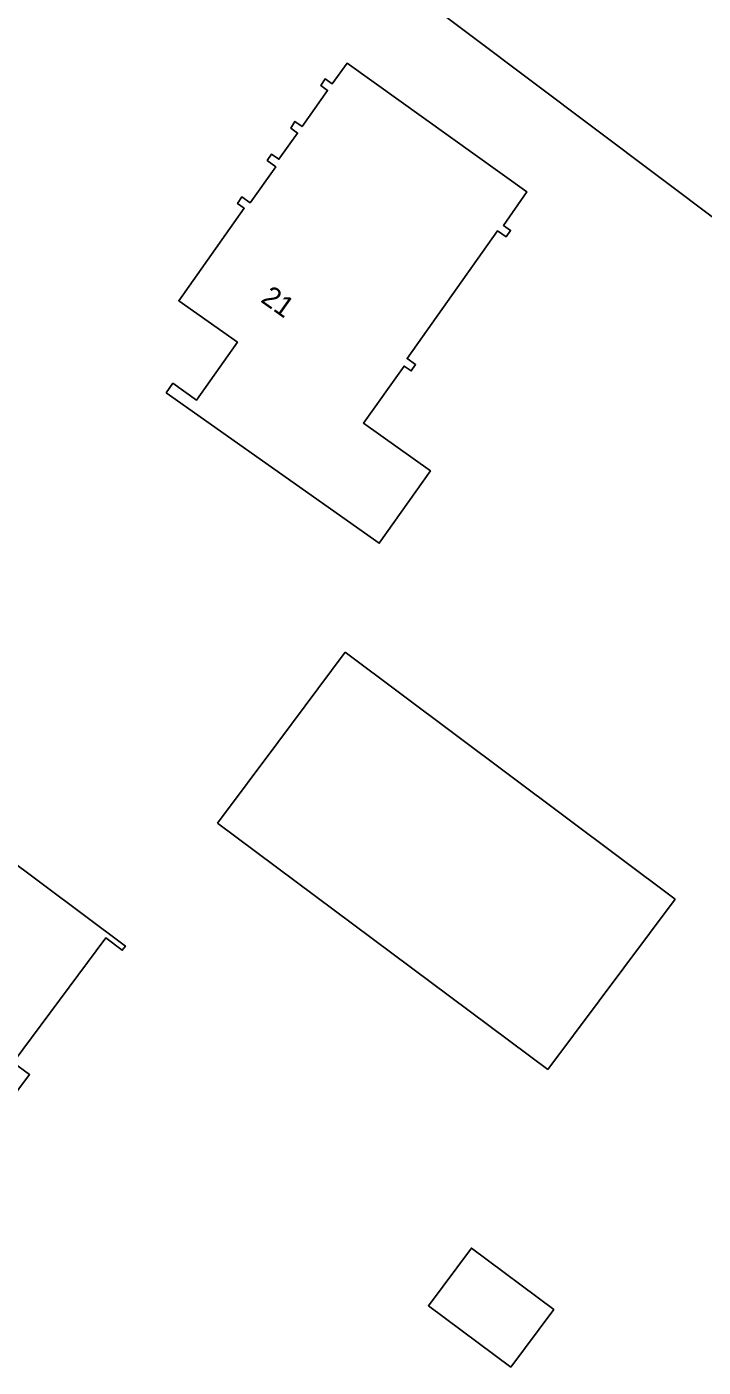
# Model space of a CAD drawing. Extents: x 136000 to 141000, y 400494 to 402006.
# Drawn here: x 137180.1 to 137213, y 400744.6 to 400809.8 of the extents above; entities that cross this region are included whole.
import ezdxf

# ---------------------------------------------------------------- set-up
doc = ezdxf.new("R2010")
doc.units = 0
for name, color, linetype in [('gg-anno-huisnummerreeks BGT', 7, 'Continuous'), ('gg-bbg-gedigitaliseerde bijgebouw', 7, 'Continuous'), ('gg-bbg-hoofdgebouw', 7, 'Continuous'), ('gg-knt-bronhoudergrens', 7, 'Continuous')]:
    doc.layers.add(name, color=color, linetype=linetype)

msp = doc.modelspace()

# ---------------------------------------------------------------- linework, layer by layer
at = {"layer": 'gg-bbg-gedigitaliseerde bijgebouw'}
for p, q in [((137192.334, 400774.993), (137195.608, 400779.388)), ((137195.608, 400779.388), (137211.678, 400767.36)), ((137189.403, 400771.058), (137192.334, 400774.993)), ((137205.484, 400759.079), (137189.403, 400771.058)), ((137205.484, 400759.079), (137211.678, 400767.36))]:
    msp.add_line(p, q, dxfattribs=at)
msp.add_lwpolyline([(137203.673, 400744.596), (137205.767, 400747.4), (137201.76, 400750.392), (137199.667, 400747.587), (137203.673, 400744.596)], dxfattribs=at)
at = {"layer": 'gg-bbg-hoofdgebouw'}
for points in [[(137186.906, 400791.996), (137187.234, 400792.465), (137188.383, 400791.647), (137190.372, 400794.462), (137187.519, 400796.479), (137190.702, 400800.977), (137190.381, 400801.204), (137190.583, 400801.53), (137190.988, 400801.243), (137192.235, 400802.986), (137191.82, 400803.302), (137192.035, 400803.611), (137192.389, 400803.361), (137193.297, 400804.639), (137192.963, 400804.881), (137193.167, 400805.2), (137193.518, 400804.95), (137194.762, 400806.714), (137194.426, 400806.952), (137194.635, 400807.267), (137194.98, 400807.024), (137195.706, 400808.031), (137204.462, 400801.774), (137203.314, 400800.145), (137203.662, 400799.897), (137203.441, 400799.589), (137203.035, 400799.881), (137198.627, 400793.665), (137199.038, 400793.371), (137198.831, 400793.066), (137198.483, 400793.301), (137196.505, 400790.527), (137199.76, 400788.204), (137197.271, 400784.685), (137186.906, 400791.996)], [(137176.86, 400771.091), (137184.918, 400765.082), (137184.768, 400764.881), (137183.966, 400765.479), (137179.452, 400759.426), (137180.253, 400758.828), (137175.766, 400752.818), (137168.53, 400758.22)]]:
    msp.add_lwpolyline(points, dxfattribs=at)
at = {"layer": 'gg-knt-bronhoudergrens'}
msp.add_lwpolyline([(137243.097, 400778.414), (137232.266, 400786.455), (137183.268, 400823.257)], dxfattribs=at)

# ---------------------------------------------------------------- texts
at = {"layer": 'gg-anno-huisnummerreeks BGT'}
msp.add_text('21', height=1, rotation=324.7, dxfattribs=at).set_placement((137191.453, 400796.458))

doc.saveas('drawing.dxf')
